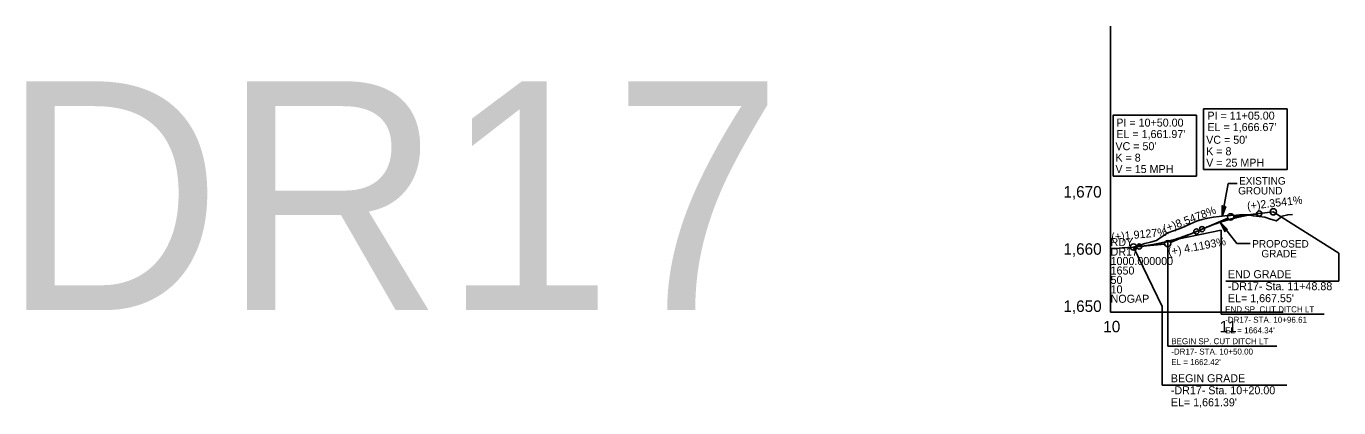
# Model space of a CAD drawing. Extents: x 498575 to 532350, y 405181 to 484585.
# Drawn here: x 526335 to 527483, y 444320 to 444654 of the extents above; entities that cross this region are included whole.
import ezdxf

# ---------------------------------------------------------------- set-up
doc = ezdxf.new("R2010")
doc.units = 0
for name, color, linetype in [('Exist Profile Cell', 7, 'Continuous'), ('Exist Vertical Profile Ground Line', 7, 'Continuous'), ('Exist Vertical Profile Horizontal Axis Label Major', 7, 'Continuous'), ('Exist Vertical Profile Vertical Axis Label', 7, 'Continuous'), ('Prop Grid Mask', 7, 'Continuous'), ('Prop PFL Text', 7, 'Continuous'), ('Prop Vertical Profile Curve Label', 7, 'Continuous'), ('Prop Vertical Profile Ditch Grade Left', 7, 'Continuous'), ('Prop Vertical Profile Ditch Grade Left Label', 7, 'Continuous'), ('Prop Vertical Profile Grade', 7, 'Continuous'), ('Prop Vertical Profile Grade Label', 7, 'Continuous'), ('Prop VPI Label', 7, 'Continuous'), ('Scratch_Level_7', 7, 'Continuous')]:
    doc.layers.add(name, color=color, linetype=linetype)

msp = doc.modelspace()

# ---------------------------------------------------------------- linework, layer by layer
at = {"layer": 'Exist Profile Cell'}
for q in [(527283.8, 444653.7), (527434.7, 444403.7), (527283.8, 444403.7)]:
    msp.add_line((527283.8, 444403.7), q, dxfattribs=at)
at = {"layer": 'Exist Vertical Profile Ground Line'}
msp.add_lwpolyline([(527283.8, 444459.4), (527288.8, 444459.5), (527293.8, 444459.9), (527298.8, 444460.4), (527303.8, 444460.7), (527308.8, 444462.2), (527313.8, 444463.8), (527318.8, 444465.1), (527323.8, 444466.4), (527328.8, 444469.9), (527333.8, 444473), (527338.8, 444474.9), (527343.8, 444476.7), (527348.8, 444478.7), (527353.8, 444481), (527358.8, 444483.4), (527363.8, 444484.7), (527368.8, 444486), (527373.8, 444486.9), (527378.8, 444487.4), (527383.8, 444488), (527388.8, 444488.4), (527393.8, 444488.7), (527398.8, 444489.1), (527403.8, 444488.9), (527408.8, 444488), (527413.8, 444487.5), (527418.8, 444486.8), (527423.8, 444485.2), (527428.8, 444483.6), (527433.8, 444487.6), (527438.8, 444488.9), (527443, 444489.1)], dxfattribs=at)
at = {"layer": 'Prop Grid Mask'}
for points in [[(527285.9, 444522.8), (527358.9, 444522.8), (527358.9, 444575.9), (527285.9, 444575.9)], [(527365.2, 444528.4), (527438.2, 444528.4), (527438.2, 444581.5), (527365.2, 444581.5)]]:
    msp.add_lwpolyline(points, close=True, dxfattribs=at)
at = {"layer": 'Prop PFL Text'}
for p, q in [((527381.3, 444487.7), (527386.5, 444516.4)), ((527386.5, 444516.4), (527394.6, 444516.4)), ((527394.1, 444463.8), (527379.5, 444482.4)), ((527394.1, 444463.8), (527405.9, 444463.8))]:
    msp.add_line(p, q, dxfattribs=at)
for points in [[(527384.6, 444496.2), (527381.3, 444487.7), (527381.5, 444496.9), (527382.9, 444495.5)], [(527386.2, 444476.1), (527379.5, 444482.4), (527383.8, 444474.2), (527384.3, 444476.1)]]:
    msp.add_lwpolyline(points, close=True, dxfattribs=at)
at = {"layer": 'Prop Vertical Profile Curve Label'}
for centre in [(527413.8, 444490), (527363.8, 444476.4), (527358.8, 444474.3), (527308.8, 444461.2)]:
    msp.add_circle(centre, 2.25, dxfattribs=at)
at = {"layer": 'Prop Vertical Profile Ditch Grade Left'}
msp.add_line((527333.8, 444465.8), (527380.4, 444475.4), dxfattribs=at)
at = {"layer": 'Prop Vertical Profile Ditch Grade Left Label'}
for p, q in [((527380.4, 444475.4), (527380.4, 444402.1)), ((527333.8, 444465.8), (527333.8, 444374.2)), ((527470.7, 444402.1), (527380.4, 444402.1)), ((527429.1, 444374.2), (527333.8, 444374.2))]:
    msp.add_line(p, q, dxfattribs=at)
at = {"layer": 'Prop Vertical Profile Grade'}
for p, q in [((527413.8, 444490), (527426.1, 444491.5)), ((527358.8, 444474.3), (527363.8, 444476.4)), ((527303.8, 444460.7), (527308.8, 444461.2))]:
    msp.add_line(p, q, dxfattribs=at)
for points in [[(527363.8, 444476.4), (527364.8, 444476.8), (527365.8, 444477.2), (527366.8, 444477.6), (527367.8, 444478.1), (527368.8, 444478.5), (527369.8, 444478.8), (527370.8, 444479.2), (527371.8, 444479.6), (527372.8, 444480), (527373.8, 444480.4), (527374.8, 444480.7), (527375.8, 444481.1), (527376.8, 444481.4), (527377.8, 444481.8), (527378.8, 444482.1), (527379.8, 444482.4), (527380.8, 444482.8), (527381.8, 444483.1), (527382.8, 444483.4), (527383.8, 444483.7), (527384.8, 444484), (527385.8, 444484.3), (527386.8, 444484.6), (527387.8, 444484.9), (527388.8, 444485.1), (527389.8, 444485.4), (527390.8, 444485.7), (527391.8, 444485.9), (527392.8, 444486.2), (527393.8, 444486.4), (527394.8, 444486.7), (527395.8, 444486.9), (527396.8, 444487.1), (527397.8, 444487.3), (527398.8, 444487.6), (527399.8, 444487.8), (527400.8, 444488), (527401.8, 444488.2), (527402.8, 444488.4), (527403.8, 444488.5), (527404.8, 444488.7), (527405.8, 444488.9), (527406.8, 444489), (527407.8, 444489.2), (527408.8, 444489.4), (527409.8, 444489.5), (527410.8, 444489.6), (527411.8, 444489.8), (527412.8, 444489.9), (527413.8, 444490)], [(527308.8, 444461.2), (527309.8, 444461.3), (527310.8, 444461.4), (527311.8, 444461.5), (527312.8, 444461.6), (527313.8, 444461.7), (527314.8, 444461.9), (527315.8, 444462), (527316.8, 444462.2), (527317.8, 444462.3), (527318.8, 444462.5), (527319.8, 444462.6), (527320.8, 444462.8), (527321.8, 444463), (527322.8, 444463.2), (527323.8, 444463.4), (527324.8, 444463.6), (527325.8, 444463.8), (527326.8, 444464), (527327.8, 444464.2), (527328.8, 444464.4), (527329.8, 444464.7), (527330.8, 444464.9), (527331.8, 444465.1), (527332.8, 444465.4), (527333.8, 444465.6), (527334.8, 444465.9), (527335.8, 444466.2), (527336.8, 444466.5), (527337.8, 444466.7), (527338.8, 444467), (527339.8, 444467.3), (527340.8, 444467.6), (527341.8, 444468), (527342.8, 444468.3), (527343.8, 444468.6), (527344.8, 444468.9), (527345.8, 444469.3), (527346.8, 444469.6), (527347.8, 444470), (527348.8, 444470.3), (527349.8, 444470.7), (527350.8, 444471.1), (527351.8, 444471.4), (527352.8, 444471.8), (527353.8, 444472.2), (527354.8, 444472.6), (527355.8, 444473), (527356.8, 444473.4), (527357.8, 444473.8), (527358.8, 444474.3)]]:
    msp.add_spline(points, degree=3, dxfattribs=at)
at = {"layer": 'Prop VPI Label'}
for p, q in [((527413.8, 444490), (527391.5, 444487.4)), ((527426.1, 444491.5), (527483.4, 444455.3)), ((527363.8, 444476.4), (527386.3, 444486)), ((527358.8, 444474.3), (527336.3, 444464.7)), ((527328.9, 444408.6), (527303.8, 444460.7)), ((527308.8, 444461.2), (527331.1, 444463.3)), ((527483.4, 444455.3), (527483.4, 444431)), ((527384.6, 444431), (527483.4, 444431)), ((527328.9, 444408.6), (527328.9, 444340)), ((527328.9, 444340), (527438.1, 444340))]:
    msp.add_line(p, q, dxfattribs=at)
for centre in [(527426.1, 444491.5), (527388.8, 444487.1), (527303.8, 444460.7), (527333.8, 444463.6)]:
    msp.add_circle(centre, 2.75, dxfattribs=at)

# ---------------------------------------------------------------- texts
at = {"layer": 'Exist Profile Cell'}
for s, p in [('RDY', (527283.8, 444461.5)), ('DR17', (527283.8, 444453.2)), ('1000.000000', (527283.8, 444445)), ('50', (527283.8, 444428.5)), ('1650', (527283.8, 444436.7)), ('10', (527283.8, 444420.2)), ('NOGAP', (527283.8, 444412))]:
    msp.add_text(s, height=7, dxfattribs=at).set_placement(p)
at = {"layer": 'Exist Vertical Profile Horizontal Axis Label Major'}
for s, p in [('10', (527277.4, 444386.2)), ('11', (527379.2, 444386.2))]:
    msp.add_text(s, height=10, dxfattribs=at).set_placement(p)
at = {"layer": 'Exist Vertical Profile Vertical Axis Label'}
for s, p in [('1,670', (527242.5, 444504)), ('1,660', (527242.5, 444454)), ('1,650', (527242.5, 444404))]:
    msp.add_text(s, height=10, dxfattribs=at).set_placement(p)
at = {"layer": 'Prop PFL Text'}
for s, p in [('GROUND', (527395.4, 444506.7)), ('EXISTING ', (527396.2, 444515.3)), ('PROPOSED ', (527407.7, 444460.3)), ('GRADE', (527415.7, 444451.7))]:
    msp.add_text(s, height=6.52, dxfattribs=at).set_placement(p)
at = {"layer": 'Prop Vertical Profile Curve Label'}
for s, p in [('V = 25 MPH ', (527367.4, 444531)), ('V = 15 MPH ', (527288, 444525.4))]:
    msp.add_text(s, height=7, dxfattribs=at).set_placement(p)
at = {"layer": 'Prop Vertical Profile Ditch Grade Left Label'}
for s, height, rotation, p in [('(+) 4.1193%', 7, 10.648, (527334.7, 444453)), ('-DR17- STA. 10+96.61', 5.25, 360, (527384, 444394.5)), ('END SP. CUT DITCH LT', 5.25, 360, (527384, 444403.7)), ("EL = 1664.34'", 5.25, 360, (527384, 444385.3)), ('BEGIN SP. CUT DITCH LT', 5.25, 360, (527336.8, 444375.8)), ('-DR17- STA. 10+50.00', 5.25, 360, (527336.8, 444366.7)), ("EL = 1662.42'", 5.25, 360, (527336.8, 444357.5))]:
    msp.add_text(s, height=height, rotation=rotation, dxfattribs=at).set_placement(p)
at = {"layer": 'Prop Vertical Profile Grade Label'}
for s, rotation, p in [('(+)2.3541%', 6.713, (527403.6, 444493)), ('(+)8.5478%', 20.6252, (527331.2, 444473.1)), ('(+)1.9127%', 5.4629, (527284.8, 444466))]:
    msp.add_text(s, height=7, rotation=rotation, dxfattribs=at).set_placement(p)
at = {"layer": 'Prop VPI Label'}
for s, p in [('PI = 10+50.00', (527288.8, 444566)), ('PI = 11+05.00', (527368.5, 444572.1)), ("EL = 1,661.97'", (527288.8, 444556)), ("EL = 1,666.67'", (527368.5, 444562.1)), ("VC = 50'", (527288, 444545.4)), ("VC = 50'", (527367.4, 444551)), ('K = 8', (527367.4, 444541)), ('K = 8', (527288, 444535.4)), ('END GRADE', (527386.4, 444433.5)), ('-DR17- Sta. 11+48.88', (527386.4, 444423)), ("EL= 1,667.55'", (527386.4, 444412.5)), ('BEGIN GRADE', (527336.5, 444342.5)), ('-DR17- Sta. 10+20.00', (527336.5, 444332)), ("EL= 1,661.39'", (527336.5, 444321.5))]:
    msp.add_text(s, height=7, dxfattribs=at).set_placement(p)
at = {"layer": 'Scratch_Level_7'}
msp.add_text('DR17', height=200, dxfattribs=at).set_placement((526313.2, 444405.6))

doc.saveas('drawing.dxf')
